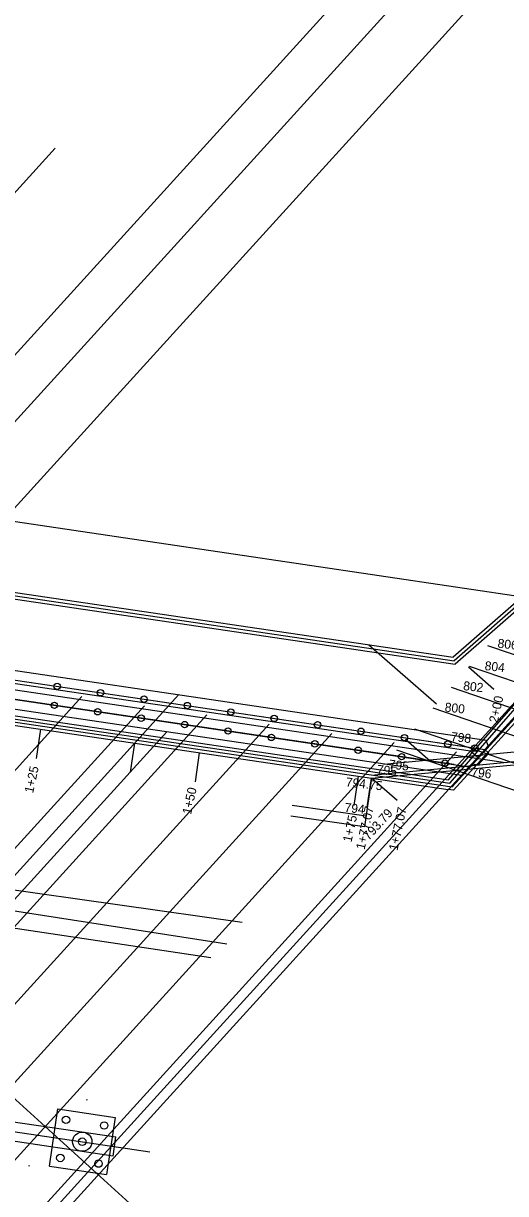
# Model space of a CAD drawing. Extents: x 1465887 to 1476191, y 569684 to 581027.
# Drawn here: x 1469977.6 to 1470052.7, y 574066.2 to 574248.6 of the extents above; entities that cross this region are included whole.
import ezdxf

# ---------------------------------------------------------------- set-up
doc = ezdxf.new("R2010")
doc.units = 0
for name, color, linetype in [('BR_P_Beam_Centerline', 7, 'Continuous'), ('BR_P_Brg_Centerline', 7, 'Continuous'), ('BR_P_Gen_Approach_Slab', 7, 'Continuous'), ('BR_P_Gen_Ground_Slope', 7, 'Continuous'), ('BR_P_Gen_Perforated_Pipe', 7, 'Continuous'), ('BR_P_Gen_Phase_Construction', 7, 'Continuous'), ('BR_P_Gen_Porous_Backfill', 7, 'Continuous'), ('BR_P_Gen_Profile_Grade', 7, 'Continuous'), ('BR_P_Gen_Slope_Protection', 7, 'Continuous'), ('BR_P_Rail_Object', 7, 'Continuous'), ('BR_P_Sub_Centerline', 7, 'Continuous'), ('BR_P_Sub_Deep_Centerline', 7, 'Continuous'), ('BR_P_Sub_Deep_Hidden', 7, 'Continuous'), ('BR_P_Sub_Foot_Hidden', 7, 'Continuous'), ('BR_P_Sub_Hidden', 7, 'Continuous'), ('BR_P_Sub_Object', 7, 'Continuous'), ('PV_X_EOP', 7, 'Continuous'), ('PV_X_Shoulder', 7, 'Continuous'), ('SC_Scratch1', 7, 'Continuous'), ('UT_X_Water', 7, 'Continuous')]:
    doc.layers.add(name, color=color, linetype=linetype)

msp = doc.modelspace()

# ---------------------------------------------------------------- linework, layer by layer
at = {"layer": 'BR_P_Beam_Centerline'}
for p, q in [((1469875.67, 574021.39), (1469986.74, 574143.69)), ((1469885.4, 574019.95), (1469996.47, 574142.25)), ((1469895.12, 574018.51), (1470006.19, 574140.81)), ((1469904.85, 574017.07), (1470015.91, 574139.37)), ((1469914.57, 574015.63), (1470025.64, 574137.93)), ((1469924.3, 574014.19), (1470035.36, 574136.49)), ((1469934.02, 574012.75), (1470045.09, 574135.05))]:
    msp.add_line(p, q, dxfattribs=at)
at = {"layer": 'BR_P_Brg_Centerline'}
msp.add_line((1469894.04, 574156.91), (1470052.69, 574133.42), dxfattribs=at)
at = {"layer": 'BR_P_Gen_Approach_Slab'}
for p, q in [((1469928.13, 574178.07), (1470067.44, 574157.44)), ((1469907.96, 574155.86), (1470047.28, 574135.23))]:
    msp.add_line(p, q, dxfattribs=at)
at = {"layer": 'BR_P_Gen_Ground_Slope'}
for p, q in [((1469967.36, 574212.34), (1469982.61, 574229.14)), ((1470049.91, 574151.65), (1470083.71, 574140.02)), ((1470047.07, 574148.4), (1470081.96, 574136.39)), ((1470044.23, 574145.14), (1470079.36, 574133.06)), ((1470041.4, 574141.89), (1470078.05, 574129.27)), ((1470033.76, 574133.13), (1470075.82, 574137.1)), ((1470038.56, 574138.64), (1470077.23, 574125.33)), ((1470032.33, 574131.49), (1470075.96, 574135.6)), ((1470035.72, 574135.38), (1470079.31, 574120.38)), ((1470031.85, 574130.95), (1470076, 574135.11)), ((1470031.85, 574130.95), (1470030.75, 574123.37)), ((1470030.99, 574125.03), (1470019.5, 574126.7)), ((1470030.75, 574123.37), (1470019.26, 574125.03))]:
    msp.add_line(p, q, dxfattribs=at)
at = {"layer": 'BR_P_Gen_Perforated_Pipe'}
for p, q in [((1470076.51, 574177.1), (1470044.7, 574149.26)), ((1470076.84, 574176.72), (1470044.86, 574148.73)), ((1470043.82, 574130.69), (1470080.98, 574173.29)), ((1470044.02, 574130.16), (1470081.36, 574172.96)), ((1469917.24, 574168.13), (1470044.7, 574149.26)), ((1469916.98, 574167.66), (1470044.86, 574148.73)), ((1469900.89, 574151.85), (1470043.82, 574130.69)), ((1469899.72, 574150.51), (1469997.64, 574061.59)), ((1469900.5, 574151.4), (1470044.02, 574130.16))]:
    msp.add_line(p, q, dxfattribs=at)
at = {"layer": 'BR_P_Gen_Phase_Construction'}
for p, q in [((1469886.75, 574017.22), (1470001.86, 574143.98)), ((1469892.16, 574019.46), (1469999.98, 574138.19))]:
    msp.add_line(p, q, dxfattribs=at)
at = {"layer": 'BR_P_Gen_Porous_Backfill'}
for p in [(1470076.18, 574177.48), (1469917.5, 574168.6)]:
    msp.add_line(p, (1470044.55, 574149.79), dxfattribs=at)
at = {"layer": 'BR_P_Gen_Profile_Grade'}
msp.add_line((1465892.5, 569689.56), (1476184.47, 581022.69), dxfattribs=at)
at = {"layer": 'BR_P_Gen_Slope_Protection'}
for p, q in [((1470044.4, 574129.59), (1470082.72, 574171.78)), ((1470044.6, 574129.06), (1470083.08, 574171.44)), ((1469899.72, 574150.51), (1470043.8, 574129.18)), ((1469900.11, 574150.95), (1470044.4, 574129.59)), ((1470044.6, 574129.06), (1470043.8, 574129.18))]:
    msp.add_line(p, q, dxfattribs=at)
at = {"layer": 'BR_P_Rail_Object'}
for p, q in [((1469915.23, 573989.83), (1470067.44, 574157.44)), ((1469923.07, 573996.23), (1470068.55, 574156.43)), ((1470047.28, 574135.23), (1470048.39, 574134.22))]:
    msp.add_line(p, q, dxfattribs=at)
at = {"layer": 'BR_P_Sub_Centerline'}
msp.add_line((1469838.73, 574096.23), (1469997.31, 574072.75), dxfattribs=at)
at = {"layer": 'BR_P_Sub_Deep_Centerline'}
for p, q in [((1469903.37, 574157.04), (1470048.77, 574135.52)), ((1470044.7, 574133.09), (1469905.02, 574153.77))]:
    msp.add_line(p, q, dxfattribs=at)
at = {"layer": 'BR_P_Sub_Deep_Hidden'}
for centre, radius in [((1469982.89, 574145.27), 0.5), ((1469989.65, 574144.27), 0.5), ((1469982.46, 574142.3), 0.5), ((1469996.42, 574143.27), 0.5), ((1470003.17, 574142.27), 0.5), ((1469989.21, 574141.3), 0.5), ((1469995.98, 574140.3), 0.5), ((1470009.93, 574141.27), 0.5), ((1470016.69, 574140.27), 0.5), ((1470002.74, 574139.3), 0.5), ((1470023.45, 574139.27), 0.5), ((1470009.5, 574138.3), 0.5), ((1470016.25, 574137.3), 0.5), ((1470030.21, 574138.26), 0.5), ((1470036.97, 574137.26), 0.5), ((1470023.01, 574136.3), 0.5), ((1470029.77, 574135.3), 0.5), ((1470043.73, 574136.26), 0.5), ((1470047.94, 574135.64), 0.5), ((1470036.53, 574134.3), 0.5), ((1470043.29, 574133.3), 0.5), ((1469984.27, 574077.72), 0.583), ((1469990.21, 574076.84), 0.583), ((1469986.8, 574074.31), 0.583), ((1469983.39, 574071.78), 0.583), ((1469989.33, 574070.9), 0.583)]:
    msp.add_circle(centre, radius, dxfattribs=at)
at = {"layer": 'BR_P_Sub_Foot_Hidden'}
for p, q in [((1469898.76, 574159.24), (1470049.69, 574136.9)), ((1469899.66, 574153.04), (1470045.83, 574131.4)), ((1470049.47, 574135.41), (1470050.01, 574136.01)), ((1470050.01, 574136.01), (1470049.69, 574136.9)), ((1470045.83, 574131.4), (1470047.44, 574133.19)), ((1469981.69, 574070.52), (1469983.01, 574079.42)), ((1469983.01, 574079.42), (1469991.91, 574078.1)), ((1469991.91, 574078.1), (1469990.59, 574069.2)), ((1469981.69, 574070.52), (1469990.59, 574069.2))]:
    msp.add_line(p, q, dxfattribs=at)
at = {"layer": 'BR_P_Sub_Hidden'}
for p, q in [((1469906.58, 574156.57), (1470049.47, 574135.41)), ((1469904.15, 574153.9), (1470047.04, 574132.74)), ((1470050.09, 574134.87), (1470048.44, 574133.04)), ((1469943.99, 574082.16), (1469992.05, 574075.05)), ((1469991.61, 574072.08), (1469943.55, 574079.2)), ((1469991.61, 574072.08), (1469992.05, 574075.05))]:
    msp.add_line(p, q, dxfattribs=at)
msp.add_circle((1469986.8, 574074.31), 1.5, dxfattribs=at)
at = {"layer": 'BR_P_Sub_Object'}
for p, q in [((1470049.47, 574135.41), (1470050.09, 574134.87)), ((1470047.04, 574132.74), (1470047.44, 574133.19)), ((1470047.44, 574133.19), (1470048.44, 574133.04))]:
    msp.add_line(p, q, dxfattribs=at)
at = {"layer": 'PV_X_EOP'}
for p, q in [((1469904.79, 574118.39), (1470006.8, 574102.99)), ((1469987.6, 574080.79), (1469987.46, 574080.82)), ((1469978.66, 574070.51), (1469978.49, 574070.54))]:
    msp.add_line(p, q, dxfattribs=at)
at = {"layer": 'PV_X_Shoulder'}
msp.add_line((1469908.94, 574123), (1470011.71, 574108.53), dxfattribs=at)
at = {"layer": 'SC_Scratch1'}
for p, q in [((1465887.32, 569694.27), (1476179.29, 581027.4)), ((1465899.17, 569683.51), (1476191.13, 581016.64)), ((1470031.41, 574151.74), (1470041.96, 574142.53)), ((1470050.89, 574144.76), (1470046.92, 574148.23)), ((1469979.67, 574134.04), (1469980.35, 574138.57)), ((1469994.31, 574131.87), (1469994.98, 574136.4)), ((1470041.08, 574133.51), (1470037.11, 574136.97)), ((1470004.41, 574130.38), (1470005.08, 574134.91)), ((1470029.14, 574126.72), (1470029.81, 574131.25)), ((1470031.18, 574126.42), (1470031.85, 574130.95)), ((1470035.82, 574127.48), (1470031.85, 574130.95))]:
    msp.add_line(p, q, dxfattribs=at)
at = {"layer": 'UT_X_Water'}
msp.add_line((1469907.74, 574120.94), (1470009.3, 574105.12), dxfattribs=at)

# ---------------------------------------------------------------- texts
at = {"layer": 'BR_P_Gen_Ground_Slope'}
for s, rotation, p in [('806', 353.6662, (1470051.42, 574151.3)), ('804', 353.6662, (1470049.41, 574147.81)), ('802', 353.6662, (1470046.07, 574144.69)), ('800', 353.6662, (1470043.19, 574141.36)), ('798', 353.6662, (1470044.16, 574136.76)), ('795', 353.6662, (1470034.48, 574132.46)), ('795', 353.6662, (1470032.62, 574131.65)), ('796', 353.6662, (1470047.33, 574131.24)), ('794.75', 353.6662, (1470027.79, 574129.68)), ('794', 353.6662, (1470027.59, 574125.72)), ('793.79', 47.7564, (1470031.4, 574121.18))]:
    msp.add_text(s, height=1.4, rotation=rotation, dxfattribs=at).set_placement(p)
at = {"layer": 'SC_Scratch1'}
for s, p in [('2+00', (1470051.49, 574139.49)), ('1+25', (1469979.15, 574128.55)), ('1+50', (1470003.74, 574125.23)), ('1+77.07', (1470030.76, 574119.73)), ('1+77.07', (1470035.88, 574119.59)), ('1+75', (1470028.72, 574120.9))]:
    msp.add_text(s, height=1.4, rotation=77.7564, dxfattribs=at).set_placement(p)

doc.saveas('drawing.dxf')
